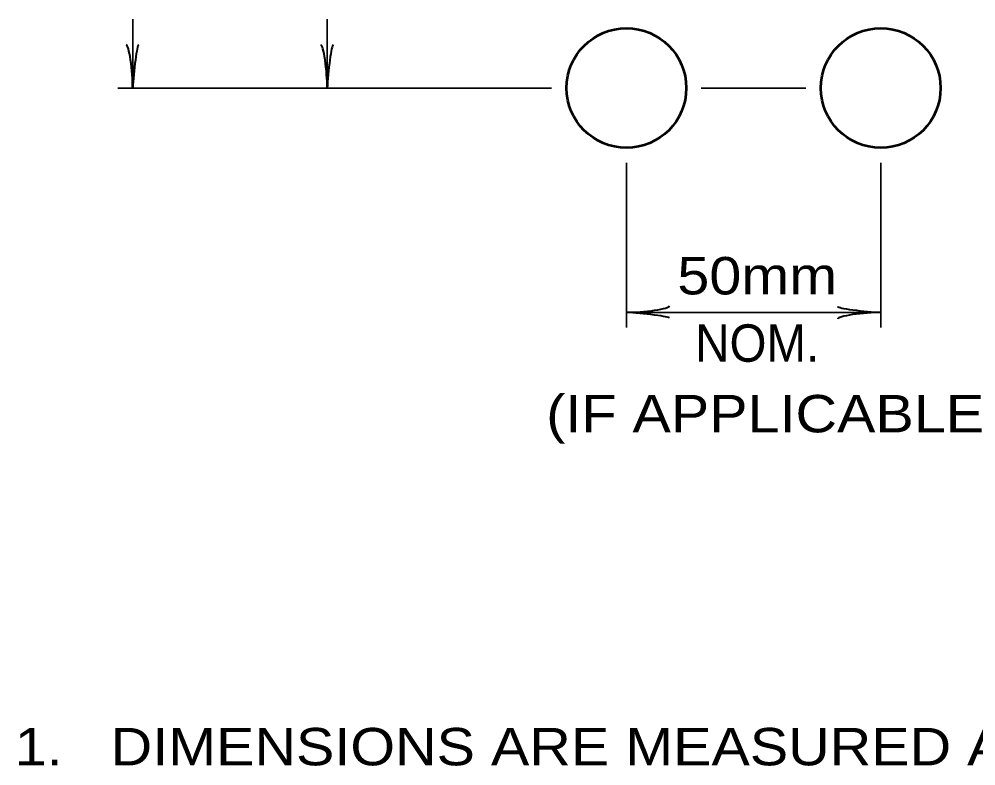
# Model space of a CAD drawing. Extents: x -50 to 806, y -9 to 535.
# Drawn here: x 392.3 to 469, y 113.9 to 173.8 of the extents above; entities that cross this region are included whole.
import ezdxf
from ezdxf.enums import TextEntityAlignment as Align

# ---------------------------------------------------------------- set-up
doc = ezdxf.new("R2010")
doc.units = 0
doc.header["$LTSCALE"] = 1.2
doc.layers.add('1', color=7, linetype='Continuous', lineweight=35)

msp = doc.modelspace()

# ---------------------------------------------------------------- linework, layer by layer
at = {"layer": '1'}
for p, q in [((401.381, 168.227), (401.381, 173.752)), ((416.981, 168.227), (416.981, 173.752)), ((434.981, 168.227), (400.181, 168.227)), ((446.981, 168.227), (455.381, 168.227)), ((440.981, 162.227), (440.981, 149.027)), ((461.381, 162.227), (461.381, 149.027)), ((440.981, 150.227), (461.381, 150.227))]:
    msp.add_line(p, q, dxfattribs=at)
at = {"layer": '1', "lineweight": 53}
for centre in [(440.981, 168.227), (461.381, 168.227)]:
    msp.add_circle(centre, 4.8, dxfattribs=at)
at = {"layer": '1', "lineweight": 40}
for centre, major_axis, ratio, start_param, end_param in [((401.05, 169.537), (0.187, -2.143), 0.122415, 0.896353, 3.141593), ((401.05, 169.537), (0.187, -2.143), 0.122415, 0.896353, 3.141593), ((401.635, 169.572), (-0.211, -2.108), 0.07063, 3.140715, 5.41811), ((401.635, 169.572), (-0.211, -2.108), 0.07063, 3.140715, 5.41811), ((416.65, 169.537), (0.187, -2.143), 0.122415, 0.896353, 3.141593), ((416.65, 169.537), (0.187, -2.143), 0.122415, 0.896353, 3.141593), ((417.235, 169.572), (-0.211, -2.108), 0.07063, 3.140715, 5.41811), ((417.235, 169.572), (-0.211, -2.108), 0.07063, 3.140715, 5.41811), ((442.291, 150.559), (-2.143, -0.187), 0.122415, 0.896353, 3.141593), ((442.291, 150.559), (-2.143, -0.187), 0.122415, 0.896353, 3.141593), ((460.037, 150.481), (2.108, -0.211), 0.07063, 3.140715, 5.41811), ((442.326, 149.973), (-2.108, 0.211), 0.07063, 3.140715, 5.41811), ((442.326, 149.973), (-2.108, 0.211), 0.07063, 3.140715, 5.41811), ((460.072, 149.896), (2.143, 0.187), 0.122415, 0.896353, 3.141593)]:
    msp.add_ellipse(centre, major_axis=major_axis, ratio=ratio, start_param=start_param, end_param=end_param, dxfattribs=at)

# ---------------------------------------------------------------- texts
at = {"layer": '1'}
for s, width, p in [('50mm', 1.15, (451.471, 151.672)), ('NOM.', 0.95, (451.471, 146.272))]:
    msp.add_text(s, height=3, dxfattribs=dict(at, width=width)).set_placement(p, align=Align.CENTER)
at = {"layer": '1', "width": 1.15}
for s, p in [('(IF APPLICABLE)', (434.545, 140.609)), ('1.   DIMENSIONS ARE MEASURED AT POINT OF CONDUIT', (391.915, 113.903))]:
    msp.add_text(s, height=3, dxfattribs=at).set_placement(p)

doc.saveas('drawing.dxf')
